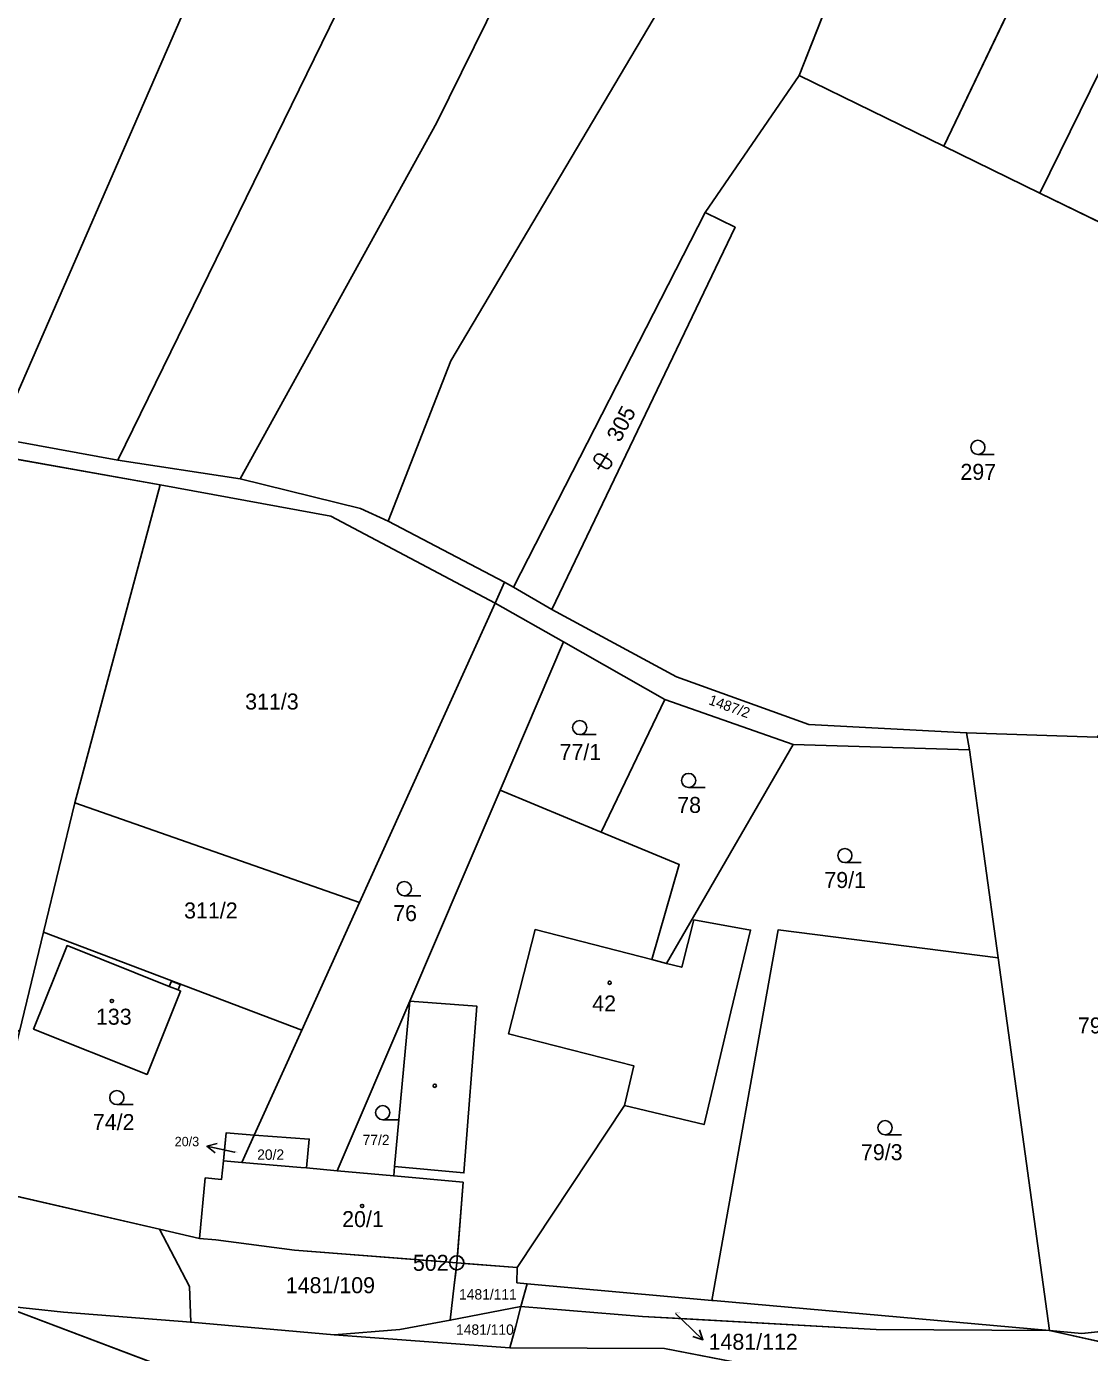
# Model space of a CAD drawing. Extents: x -760642 to -757221, y -1092371 to -1088855.
# Drawn here: x -759046.6 to -758933.7, y -1089822.5 to -1089681.5 of the extents above; entities that cross this region are included whole.
import ezdxf

# ---------------------------------------------------------------- set-up
doc = ezdxf.new("R2010")
doc.units = 0
for name, color, linetype in [('Vrstva 1', 7, 'Continuous'), ('Vrstva 16', 7, 'Continuous'), ('Vrstva 17', 7, 'Continuous'), ('Vrstva 18', 7, 'Continuous'), ('Vrstva 19', 7, 'Continuous'), ('Vrstva 24', 7, 'Continuous'), ('Vrstva 25', 7, 'Continuous'), ('Vrstva 26', 7, 'Continuous'), ('Vrstva 27', 7, 'Continuous'), ('Vrstva 4', 7, 'Continuous')]:
    doc.layers.add(name, color=color, linetype=linetype)

msp = doc.modelspace()

# ---------------------------------------------------------------- linework, layer by layer
at = {"layer": 'Vrstva 1'}
for p, q in [((-758972.3, -1089595.3), (-759036.93, -1089727.6)), ((-758957.38, -1089598.99), (-759003.05, -1089691.72)), ((-758934.28, -1089610.09), (-758964.56, -1089686.74)), ((-758916.3, -1089625.5), (-758949.19, -1089694.25)), ((-759021.95, -1089661.61), (-759049.74, -1089725.28)), ((-759001.56, -1089717.05), (-758979.5, -1089679.81)), ((-758931.48, -1089683.95), (-758938.98, -1089699.23)), ((-758964.56, -1089686.74), (-758974.54, -1089701.27)), ((-758964.56, -1089686.74), (-758949.19, -1089694.25)), ((-759003.05, -1089691.72), (-759023.94, -1089729.58)), ((-758949.19, -1089694.25), (-758938.98, -1089699.23)), ((-758938.98, -1089699.23), (-758921.61, -1089707.71)), ((-758974.54, -1089701.27), (-758994.9, -1089741.09)), ((-758974.54, -1089701.27), (-758971.37, -1089702.86)), ((-758971.37, -1089702.86), (-758990.85, -1089743.47)), ((-759008.21, -1089734.1), (-759001.56, -1089717.05)), ((-759049.74, -1089725.28), (-759036.93, -1089727.6)), ((-759032.45, -1089730.24), (-759050.46, -1089727.02)), ((-759036.93, -1089727.6), (-759023.94, -1089729.58)), ((-759023.94, -1089729.58), (-759011.15, -1089732.75)), ((-759032.45, -1089730.24), (-759041.5, -1089764.03)), ((-759032.45, -1089730.24), (-759014.31, -1089733.57)), ((-759011.15, -1089732.75), (-759008.21, -1089734.1)), ((-759014.31, -1089733.57), (-758996.87, -1089742.79)), ((-758995.87, -1089740.58), (-759008.21, -1089734.1)), ((-758996.87, -1089742.79), (-758995.87, -1089740.58)), ((-758994.9, -1089741.09), (-758995.87, -1089740.58)), ((-758994.9, -1089741.09), (-758990.85, -1089743.47)), ((-758996.87, -1089742.79), (-759011.27, -1089774.63)), ((-758996.87, -1089742.79), (-758989.59, -1089746.93)), ((-758990.85, -1089743.47), (-758977.57, -1089750.63)), ((-758989.59, -1089746.93), (-758996.33, -1089762.67)), ((-758989.59, -1089746.93), (-758978.83, -1089753.05)), ((-758977.57, -1089750.63), (-758963.52, -1089755.7)), ((-758978.83, -1089753.05), (-758985.58, -1089767.14)), ((-758978.83, -1089753.05), (-758965.18, -1089757.84)), ((-758946.76, -1089756.58), (-758963.52, -1089755.7)), ((-758932.89, -1089757.04), (-758946.76, -1089756.58)), ((-758946.76, -1089756.58), (-758946.46, -1089758.4)), ((-758965.18, -1089757.84), (-758978.66, -1089781.09)), ((-758965.18, -1089757.84), (-758946.46, -1089758.4)), ((-758943.42, -1089780.49), (-758946.46, -1089758.4)), ((-758996.33, -1089762.67), (-759000.26, -1089771.87)), ((-758996.33, -1089762.67), (-758985.58, -1089767.14)), ((-759044.84, -1089777.79), (-759041.5, -1089764.03)), ((-759041.5, -1089764.03), (-759011.27, -1089774.63)), ((-758985.58, -1089767.14), (-758977.3, -1089770.58)), ((-758980.21, -1089780.69), (-758977.3, -1089770.58)), ((-759000.26, -1089771.87), (-759005.92, -1089785.1)), ((-759011.27, -1089774.63), (-759017.39, -1089788.19)), ((-758977.03, -1089781.51), (-758975.74, -1089776.47)), ((-758975.74, -1089776.47), (-758969.72, -1089777.55)), ((-759047.4, -1089788.33), (-759044.84, -1089777.79)), ((-759044.84, -1089777.79), (-759017.39, -1089788.19)), ((-758973.83, -1089816.91), (-758966.8, -1089777.54)), ((-758969.72, -1089777.55), (-758971.8, -1089786.26)), ((-758943.42, -1089780.49), (-758966.8, -1089777.54)), ((-759042.33, -1089779.21), (-759045.89, -1089788.08)), ((-759042.33, -1089779.21), (-759031.48, -1089783.56)), ((-758980.21, -1089780.69), (-758978.66, -1089781.09)), ((-758937.97, -1089820.13), (-758943.42, -1089780.49)), ((-758978.66, -1089781.09), (-758977.03, -1089781.51)), ((-759031.25, -1089782.98), (-759031.48, -1089783.56)), ((-759030.33, -1089783.35), (-759031.25, -1089782.98)), ((-759030.55, -1089783.92), (-759030.33, -1089783.35)), ((-759033.83, -1089792.9), (-759030.27, -1089784.04)), ((-759030.27, -1089784.04), (-759030.55, -1089783.92)), ((-759005.92, -1089785.1), (-759013.63, -1089803.13)), ((-759005.92, -1089785.1), (-759007.54, -1089802.68)), ((-758971.8, -1089786.26), (-758974.66, -1089798.22)), ((-759045.89, -1089788.08), (-759033.83, -1089792.9)), ((-759017.39, -1089788.19), (-759022.45, -1089799.34)), ((-758994.51, -1089813.43), (-758983.12, -1089796.2)), ((-758974.66, -1089798.22), (-758983.12, -1089796.2)), ((-759025.45, -1089799.12), (-759025.73, -1089802.09)), ((-759022.45, -1089799.34), (-759025.45, -1089799.12)), ((-759022.45, -1089799.34), (-759023.77, -1089802.25)), ((-759016.61, -1089799.76), (-759022.45, -1089799.34)), ((-759016.89, -1089802.83), (-759016.61, -1089799.76)), ((-759025.73, -1089802.09), (-759025.92, -1089804.06)), ((-759023.77, -1089802.25), (-759025.73, -1089802.09)), ((-759017.49, -1089802.78), (-759023.77, -1089802.25)), ((-759017.49, -1089802.78), (-759016.89, -1089802.83)), ((-759013.63, -1089803.13), (-759016.89, -1089802.83)), ((-759007.63, -1089803.68), (-759013.63, -1089803.13)), ((-759007.54, -1089802.68), (-759007.63, -1089803.68)), ((-759027.65, -1089803.9), (-759028.26, -1089810.32)), ((-759025.92, -1089804.06), (-759027.65, -1089803.9)), ((-759000.26, -1089804.36), (-759007.63, -1089803.68)), ((-759000.93, -1089812.92), (-759000.26, -1089804.36)), ((-759032.5, -1089809.35), (-759051.44, -1089805)), ((-759032.5, -1089809.35), (-759029.34, -1089815.45)), ((-759028.26, -1089810.32), (-759032.5, -1089809.35)), ((-759026.53, -1089810.48), (-759028.26, -1089810.32)), ((-759018.19, -1089811.56), (-759026.53, -1089810.48)), ((-759000.93, -1089812.92), (-759018.19, -1089811.56)), ((-759001.2, -1089815.31), (-759000.93, -1089812.92)), ((-759000.93, -1089812.92), (-758994.51, -1089813.43)), ((-758994.51, -1089813.43), (-758994.55, -1089815.04)), ((-759029.34, -1089815.45), (-759029.2, -1089819.24)), ((-759001.62, -1089819.03), (-759001.2, -1089815.31)), ((-758993.47, -1089815.14), (-758994.55, -1089815.04)), ((-758994.11, -1089817.55), (-758993.47, -1089815.14)), ((-758973.83, -1089816.91), (-758993.47, -1089815.14)), ((-759021.58, -1089827.93), (-759049.32, -1089817.46)), ((-759042.71, -1089818.15), (-759049.32, -1089817.46)), ((-758973.66, -1089816.93), (-758973.83, -1089816.91)), ((-758937.97, -1089820.13), (-758973.66, -1089816.93)), ((-759029.2, -1089819.24), (-759042.71, -1089818.15)), ((-759001.62, -1089819.03), (-758994.11, -1089817.55)), ((-758994.11, -1089817.55), (-758994.67, -1089819.64)), ((-758994.11, -1089817.55), (-758981.19, -1089818.61)), ((-758981.19, -1089818.61), (-758956.38, -1089819.99)), ((-758934.53, -1089820.44), (-758916.21, -1089818.53)), ((-759013.96, -1089820.56), (-759029.2, -1089819.24)), ((-759013.96, -1089820.56), (-759006.99, -1089820.02)), ((-759006.99, -1089820.02), (-759001.62, -1089819.03)), ((-758994.67, -1089819.64), (-758995.29, -1089821.97)), ((-758956.38, -1089819.99), (-758937.97, -1089820.13)), ((-758937.97, -1089820.13), (-758934.53, -1089820.44)), ((-758937.97, -1089820.13), (-758908.4, -1089826.64)), ((-758995.29, -1089821.97), (-759013.96, -1089820.56)), ((-758978.87, -1089822.04), (-758995.29, -1089821.97)), ((-758940.36, -1089829.46), (-758978.87, -1089822.04))]:
    msp.add_line(p, q, dxfattribs=at)
at = {"layer": 'Vrstva 16'}
for p, q in [((-759024.55, -1089801.15), (-759027.486, -1089800.531)), ((-759024.5, -1089801.16), (-759024.55, -1089801.15)), ((-758977.68, -1089818.29), (-758976.94, -1089819.01)), ((-758976.94, -1089819.01), (-758974.789, -1089821.101))]:
    msp.add_line(p, q, dxfattribs=at)
for points in [[(-759026.61, -1089801.227), (-759027.486, -1089800.531), (-759026.404, -1089800.248)], [(-758975.158, -1089820.046), (-758974.789, -1089821.101), (-758975.855, -1089820.763)]]:
    msp.add_lwpolyline(points, dxfattribs=at)
at = {"layer": 'Vrstva 24'}
for radius in [0.75, 0.0327]:
    msp.add_circle((-759000.93, -1089812.92), radius, dxfattribs=at)
at = {"layer": 'Vrstva 25'}
for p, q in [((-758985.939, -1089728.576), (-758984.876, -1089726.881)), ((-758984.718, -1089727.571), (-758985.565, -1089727.039)), ((-758943.82, -1089727), (-758945.57, -1089727)), ((-758985.249, -1089728.418), (-758986.096, -1089727.886)), ((-758986.12, -1089756.78), (-758987.87, -1089756.78)), ((-758974.55, -1089762.4), (-758976.3, -1089762.4)), ((-758957.95, -1089770.38), (-758959.7, -1089770.38)), ((-759004.76, -1089773.9), (-759006.51, -1089773.9)), ((-759035.3, -1089796.11), (-759037.05, -1089796.11)), ((-759007.05, -1089797.71), (-759008.8, -1089797.71)), ((-758953.68, -1089799.31), (-758955.43, -1089799.31))]:
    msp.add_line(p, q, dxfattribs=at)
for centre, radius in [((-758945.57, -1089726.25), 0.75), ((-758987.87, -1089756.03), 0.75), ((-758976.3, -1089761.65), 0.75), ((-758959.7, -1089769.63), 0.75), ((-759006.51, -1089773.15), 0.75), ((-758984.69, -1089783.15), 0.175), ((-759037.57, -1089785.09), 0.175), ((-759037.05, -1089795.36), 0.75), ((-759003.27, -1089794.1), 0.175), ((-759008.8, -1089796.96), 0.75), ((-758955.43, -1089798.56), 0.75), ((-759010.99, -1089806.88), 0.175)]:
    msp.add_circle(centre, radius, dxfattribs=at)
for centre, start, end in [((-758985.831, -1089727.463), 57.89241, 237.89241), ((-758984.984, -1089727.994), 237.89241, 57.89241)]:
    msp.add_arc(centre, 0.5, start, end, dxfattribs=at)
at = {"layer": 'Vrstva 26'}
for points in [[(-758964.56, -1089686.74), (-758949.19, -1089694.25), (-758916.3, -1089625.5), (-758934.28, -1089610.09), (-758964.56, -1089686.74)], [(-758916.3, -1089625.5), (-758949.19, -1089694.25), (-758938.98, -1089699.23), (-758931.48, -1089683.95), (-758930.34, -1089681.62), (-758926.27, -1089673.32), (-758913.77, -1089627.67), (-758916.3, -1089625.5)], [(-758925.644, -1089683.926), (-758920.83, -1089686.29), (-758921.99, -1089688.64), (-758931.48, -1089683.95), (-758938.98, -1089699.23), (-758921.61, -1089707.71), (-758897.45, -1089655.89), (-758894.2, -1089649.19), (-758897.14, -1089645.53), (-758899.45, -1089641.9), (-758901.79, -1089638.23), (-758902.79, -1089636.72), (-758904.5, -1089640.06), (-758913.77, -1089627.67), (-758926.27, -1089673.32), (-758930.34, -1089681.62), (-758925.644, -1089683.926)], [(-758906.21, -1089715.23), (-758921.61, -1089707.71), (-758938.98, -1089699.23), (-758949.19, -1089694.25), (-758964.56, -1089686.74), (-758974.54, -1089701.27), (-758971.37, -1089702.86), (-758990.85, -1089743.47), (-758977.57, -1089750.63), (-758963.52, -1089755.7), (-758946.76, -1089756.58), (-758932.89, -1089757.04), (-758902.17, -1089717.2), (-758906.21, -1089715.23)], [(-758990.85, -1089743.47), (-758971.37, -1089702.86), (-758974.54, -1089701.27), (-758994.9, -1089741.09), (-758990.85, -1089743.47)], [(-759107.53, -1089737.24), (-759107.49, -1089742.38), (-759061.72, -1089738.64), (-759057.18, -1089782.12), (-759047.4, -1089788.33), (-759044.84, -1089777.79), (-759041.5, -1089764.03), (-759032.45, -1089730.24), (-759050.46, -1089727.02), (-759058.81, -1089724.82), (-759097.65, -1089713.08), (-759107.53, -1089737.24)], [(-759011.27, -1089774.63), (-758996.87, -1089742.79), (-759014.31, -1089733.57), (-759032.45, -1089730.24), (-759041.5, -1089764.03), (-759011.27, -1089774.63)], [(-758994.9, -1089741.09), (-758995.87, -1089740.58), (-758996.87, -1089742.79), (-758989.59, -1089746.93), (-758978.83, -1089753.05), (-758965.18, -1089757.84), (-758946.46, -1089758.4), (-758946.76, -1089756.58), (-758963.52, -1089755.7), (-758977.57, -1089750.63), (-758990.85, -1089743.47), (-758994.9, -1089741.09)], [(-758989.59, -1089746.93), (-758996.87, -1089742.79), (-759011.27, -1089774.63), (-759017.39, -1089788.19), (-759022.45, -1089799.34), (-759016.61, -1089799.76), (-759016.89, -1089802.83), (-759013.63, -1089803.13), (-759005.92, -1089785.1), (-759000.26, -1089771.87), (-758996.33, -1089762.67), (-758989.59, -1089746.93)], [(-758996.33, -1089762.67), (-758985.58, -1089767.14), (-758978.83, -1089753.05), (-758989.59, -1089746.93), (-758996.33, -1089762.67)], [(-758985.58, -1089767.14), (-758977.3, -1089770.58), (-758980.21, -1089780.69), (-758978.66, -1089781.09), (-758965.18, -1089757.84), (-758978.83, -1089753.05), (-758985.58, -1089767.14)], [(-758946.46, -1089758.4), (-758943.42, -1089780.49), (-758937.97, -1089820.13), (-758934.53, -1089820.44), (-758916.21, -1089818.53), (-758916.38, -1089811.33), (-758921.62, -1089811.49), (-758922.32, -1089788.8), (-758922.54, -1089781.57), (-758928, -1089768.73), (-758926.72, -1089767.81), (-758929.58, -1089757.04), (-758932.89, -1089757.04), (-758946.76, -1089756.58), (-758946.46, -1089758.4)], [(-758977.03, -1089781.51), (-758975.74, -1089776.47), (-758969.72, -1089777.55), (-758971.8, -1089786.26), (-758974.66, -1089798.22), (-758983.12, -1089796.2), (-758994.51, -1089813.43), (-758994.55, -1089815.04), (-758993.47, -1089815.14), (-758973.83, -1089816.91), (-758966.8, -1089777.54), (-758943.42, -1089780.49), (-758946.46, -1089758.4), (-758965.18, -1089757.84), (-758978.66, -1089781.09), (-758977.03, -1089781.51)], [(-759000.182, -1089812.979), (-758994.51, -1089813.43), (-758983.12, -1089796.2), (-758982.12, -1089792), (-758995.45, -1089788.58), (-758992.61, -1089777.51), (-758980.21, -1089780.69), (-758977.3, -1089770.58), (-758985.58, -1089767.14), (-758996.33, -1089762.67), (-759000.26, -1089771.87), (-759005.92, -1089785.1), (-758998.8, -1089785.65), (-759000.18, -1089803.37), (-759007.54, -1089802.68), (-759007.63, -1089803.68), (-759000.26, -1089804.36), (-759000.871, -1089812.172)], [(-759044.84, -1089777.79), (-759017.39, -1089788.19), (-759011.27, -1089774.63), (-759041.5, -1089764.03), (-759044.84, -1089777.79)], [(-758980.21, -1089780.69), (-758992.61, -1089777.51), (-758995.45, -1089788.58), (-758982.12, -1089792), (-758983.12, -1089796.2), (-758974.66, -1089798.22), (-758971.8, -1089786.26), (-758969.72, -1089777.55), (-758975.74, -1089776.47), (-758977.03, -1089781.51), (-758978.66, -1089781.09), (-758980.21, -1089780.69)], [(-759025.62, -1089800.924), (-759025.45, -1089799.12), (-759022.45, -1089799.34), (-759017.39, -1089788.19), (-759044.84, -1089777.79), (-759047.4, -1089788.33), (-759051.44, -1089805), (-759032.5, -1089809.35), (-759028.26, -1089810.32), (-759027.65, -1089803.9), (-759025.92, -1089804.06), (-759025.73, -1089802.09), (-759025.62, -1089800.924)], [(-758937.97, -1089820.13), (-758943.42, -1089780.49), (-758966.8, -1089777.54), (-758973.83, -1089816.91), (-758973.66, -1089816.93), (-758937.97, -1089820.13)], [(-759030.55, -1089783.92), (-759031.48, -1089783.56), (-759042.33, -1089779.21), (-759045.89, -1089788.08), (-759033.83, -1089792.9), (-759030.27, -1089784.04), (-759030.55, -1089783.92)], [(-759091.045, -1089805.166), (-759071.27, -1089811.68), (-759049.32, -1089817.46), (-759042.71, -1089818.15), (-759029.2, -1089819.24), (-759029.34, -1089815.45), (-759032.5, -1089809.35), (-759051.44, -1089805), (-759059.96, -1089803.05), (-759085.48, -1089798.88), (-759102.96, -1089790.95), (-759107.14, -1089789.05), (-759108.48, -1089788.44), (-759123.91, -1089784.65), (-759125.03, -1089784.34), (-759137.06, -1089781.89), (-759146.495, -1089779.96)], [(-759007.082, -1089797.71), (-759005.92, -1089785.1), (-759013.63, -1089803.13), (-759007.63, -1089803.68), (-759007.54, -1089802.68), (-759007.082, -1089797.71)], [(-759007.082, -1089797.71), (-759007.54, -1089802.68), (-759000.18, -1089803.37), (-758998.8, -1089785.65), (-759005.92, -1089785.1), (-759007.082, -1089797.71)], [(-759025.62, -1089800.924), (-759025.73, -1089802.09), (-759023.77, -1089802.25), (-759022.45, -1089799.34), (-759025.45, -1089799.12), (-759025.62, -1089800.924)], [(-759017.49, -1089802.78), (-759016.89, -1089802.83), (-759016.61, -1089799.76), (-759022.45, -1089799.34), (-759023.77, -1089802.25), (-759017.49, -1089802.78)], [(-759000.871, -1089812.172), (-759000.26, -1089804.36), (-759007.63, -1089803.68), (-759013.63, -1089803.13), (-759016.89, -1089802.83), (-759017.49, -1089802.78), (-759023.77, -1089802.25), (-759025.73, -1089802.09), (-759025.92, -1089804.06), (-759027.65, -1089803.9), (-759028.26, -1089810.32), (-759026.53, -1089810.48), (-759018.19, -1089811.56), (-759001.678, -1089812.861)], [(-759001.678, -1089812.861), (-759018.19, -1089811.56), (-759026.53, -1089810.48), (-759028.26, -1089810.32), (-759032.5, -1089809.35), (-759029.34, -1089815.45), (-759029.2, -1089819.24), (-759013.96, -1089820.56), (-759006.99, -1089820.02), (-759001.62, -1089819.03), (-759001.2, -1089815.31), (-759001.014, -1089813.665)], [(-759079.78, -1089818.64), (-759048.79, -1089824.35), (-759040.51, -1089825.71), (-759021.58, -1089827.93), (-759049.32, -1089817.46), (-759081.2, -1089811.04), (-759099.17, -1089811.94), (-759091.6, -1089828.44), (-759088.48, -1089844.04), (-759087.67, -1089862.1), (-759084.89, -1089862.23), (-759088.47, -1089826.4), (-759079.78, -1089818.64)], [(-759001.014, -1089813.665), (-759001.2, -1089815.31), (-759001.62, -1089819.03), (-758994.11, -1089817.55), (-758993.47, -1089815.14), (-758994.55, -1089815.04), (-758994.51, -1089813.43), (-759000.182, -1089812.979)], [(-758977.118, -1089818.836), (-758956.38, -1089819.99), (-758937.97, -1089820.13), (-758973.66, -1089816.93), (-758973.83, -1089816.91), (-758993.47, -1089815.14), (-758994.11, -1089817.55), (-758981.19, -1089818.61), (-758977.118, -1089818.836)], [(-758940.36, -1089829.46), (-758978.87, -1089822.04), (-758995.29, -1089821.97), (-759013.96, -1089820.56), (-759029.2, -1089819.24), (-759042.71, -1089818.15), (-759049.32, -1089817.46), (-759021.58, -1089827.93)], [(-759001.62, -1089819.03), (-759006.99, -1089820.02), (-759013.96, -1089820.56), (-758995.29, -1089821.97), (-758994.67, -1089819.64), (-758994.11, -1089817.55), (-759001.62, -1089819.03)], [(-758977.118, -1089818.836), (-758981.19, -1089818.61), (-758994.11, -1089817.55), (-758994.67, -1089819.64), (-758995.29, -1089821.97), (-758978.87, -1089822.04), (-758940.36, -1089829.46), (-758915.94, -1089831.98), (-758899.04, -1089835.16), (-758894.95, -1089837.25), (-758873.57, -1089841.83), (-758872.87, -1089838.03), (-758894.48, -1089831.19), (-758895.18, -1089829.55), (-758908.4, -1089826.64), (-758937.97, -1089820.13), (-758956.38, -1089819.99), (-758977.118, -1089818.836)]]:
    msp.add_lwpolyline(points, dxfattribs=at)
for centre, start, end in [((-759008.8, -1089796.96), 0, 180), ((-759008.8, -1089796.96), 180, 0), ((-759000.93, -1089812.92), 175.49469, 180), ((-759000.93, -1089812.92), 180, 263.55458), ((-759000.93, -1089812.92), 85.52452, 175.49469), ((-759000.93, -1089812.92), 263.55458, 355.458), ((-759000.93, -1089812.92), 0, 85.52452), ((-759000.93, -1089812.92), 355.458, 0)]:
    msp.add_arc(centre, 0.75, start, end, dxfattribs=at)
at = {"layer": 'Vrstva 27'}
for points in [[(-758934.28, -1089610.09), (-758964.56, -1089686.74), (-758974.54, -1089701.27), (-758994.9, -1089741.09), (-758995.87, -1089740.58), (-758996.87, -1089742.79), (-759014.31, -1089733.57), (-759032.45, -1089730.24), (-759050.46, -1089727.02), (-759097.65, -1089713.08), (-759149.45, -1089698.48), (-759161.57, -1089695.06), (-759184.67, -1089688.55), (-759196.94, -1089683.12), (-759212.4, -1089679.21)], [(-758908.4, -1089826.64), (-758937.97, -1089820.13), (-758934.53, -1089820.44), (-758916.21, -1089818.53), (-758904.26, -1089817.58), (-758900.63, -1089815.1), (-758897.32, -1089807.05), (-758895.06, -1089794.17), (-758893.33, -1089784.09), (-758888.61, -1089769.01), (-758886.42, -1089754.39), (-758880.83, -1089733.19), (-758874.22, -1089721.62), (-758872.44, -1089718.5), (-758869.61, -1089713.9), (-758857.17, -1089688.23)]]:
    msp.add_lwpolyline(points, dxfattribs=at)
at = {"layer": 'Vrstva 4'}
for p, q in [((-758995.45, -1089788.58), (-758992.61, -1089777.51)), ((-758992.61, -1089777.51), (-758980.21, -1089780.69)), ((-759031.48, -1089783.56), (-759030.55, -1089783.92)), ((-759005.92, -1089785.1), (-758998.8, -1089785.65)), ((-759000.18, -1089803.37), (-758998.8, -1089785.65)), ((-758995.45, -1089788.58), (-758982.12, -1089792)), ((-758982.12, -1089792), (-758983.12, -1089796.2)), ((-759007.54, -1089802.68), (-759000.18, -1089803.37))]:
    msp.add_line(p, q, dxfattribs=at)

# ---------------------------------------------------------------- texts
at = {"layer": 'Vrstva 16'}
for s, height, p in [('20/3', 1, (-759030.904, -1089800.53)), ('1481/112', 1.7, (-758974.18, -1089822.16))]:
    msp.add_text(s, height=height, dxfattribs=at).set_placement(p)
at = {"layer": 'Vrstva 17'}
msp.add_text('502', height=1.7, dxfattribs=at).set_placement((-759005.596, -1089813.77))
at = {"layer": 'Vrstva 18'}
for s, height, rotation, p in [('305', 1.7, 62.50185, (-758983.59, -1089725.8)), ('1487/2', 1.1, 340.30134, (-758974.264, -1089753.535))]:
    msp.add_text(s, height=height, rotation=rotation, dxfattribs=at).set_placement(p)
for s, height, p in [('297', 1.7, (-758947.424, -1089729.7)), ('311/3', 1.7, (-759023.418, -1089754.11)), ('77/1', 1.7, (-758990.013, -1089759.48)), ('78', 1.7, (-758977.508, -1089765.1)), ('79/1', 1.7, (-758961.878, -1089773.08)), ('311/2', 1.7, (-759029.906, -1089776.32)), ('76', 1.7, (-759007.69, -1089776.6)), ('79/2', 1.7, (-758934.94, -1089788.54)), ('74/2', 1.7, (-759039.6, -1089798.81)), ('77/2', 1.1, (-759010.94, -1089800.41)), ('79/3', 1.7, (-758957.992, -1089802.01)), ('1481/109', 1.7, (-759019.1, -1089816.15)), ('1481/111', 1.1, (-759000.69, -1089816.82)), ('1481/112', 0.1, (-758977.853, -1089818.29)), ('1481/110', 1.1, (-759001.01, -1089820.57))]:
    msp.add_text(s, height=height, dxfattribs=at).set_placement(p)
at = {"layer": 'Vrstva 19'}
for s, height, p in [('42', 1.7, (-758986.541, -1089786.2)), ('133', 1.7, (-759039.27, -1089787.61)), ('20/3', 0.1, (-759024.5, -1089801.16)), ('20/2', 1.1, (-759022.14, -1089801.97)), ('20/1', 1.7, (-759013.11, -1089809.12))]:
    msp.add_text(s, height=height, dxfattribs=at).set_placement(p)

doc.saveas('drawing.dxf')
